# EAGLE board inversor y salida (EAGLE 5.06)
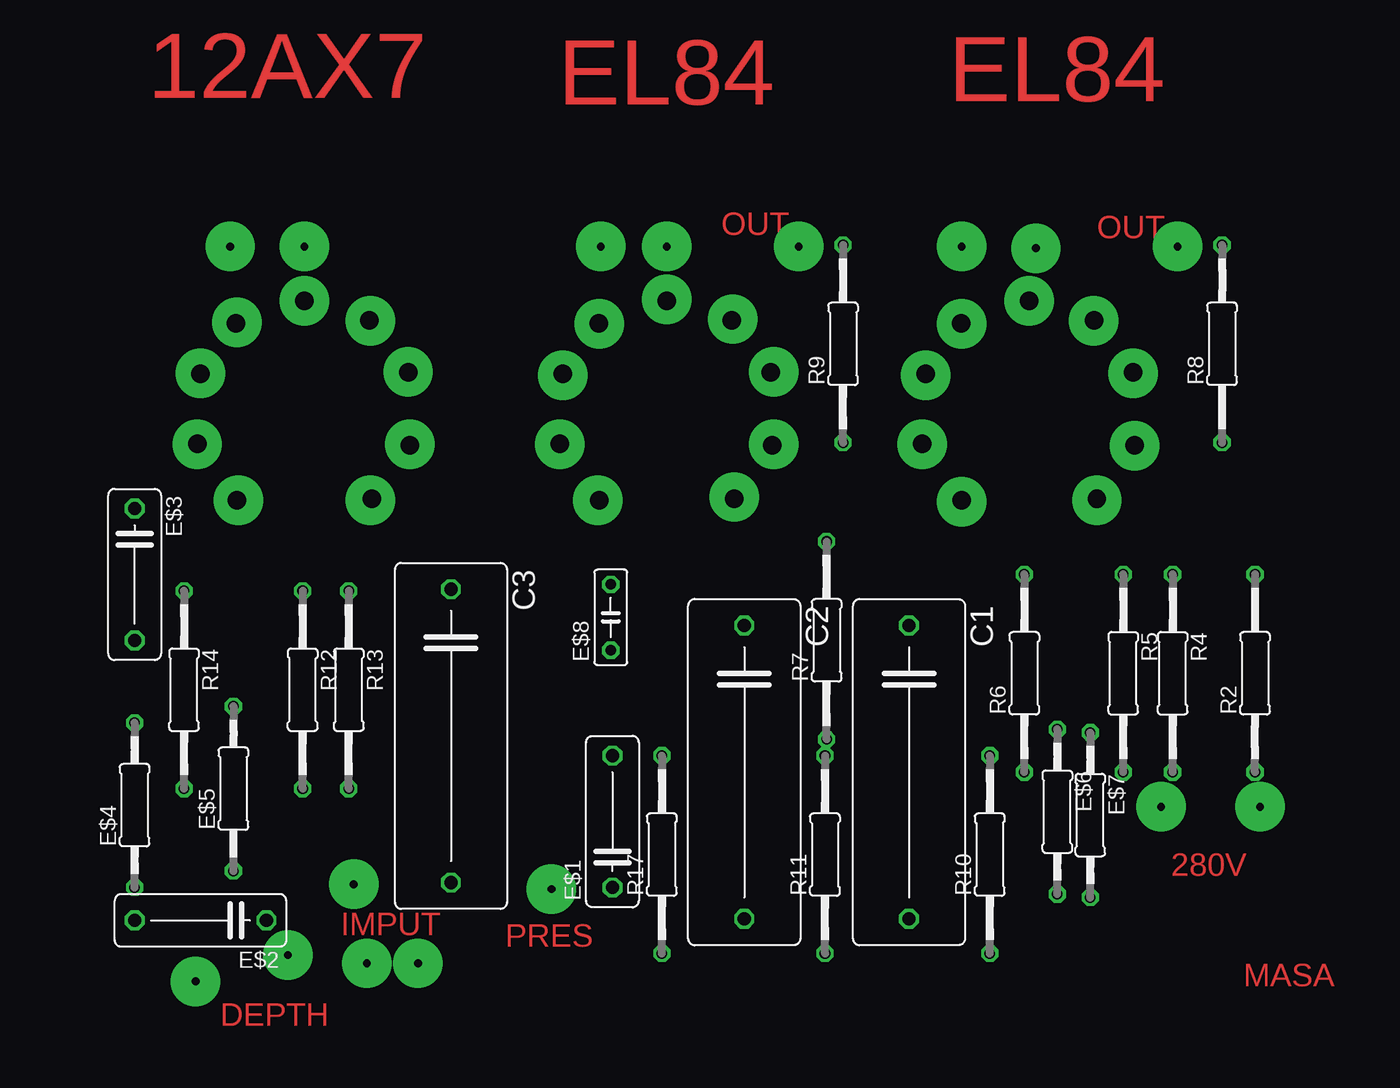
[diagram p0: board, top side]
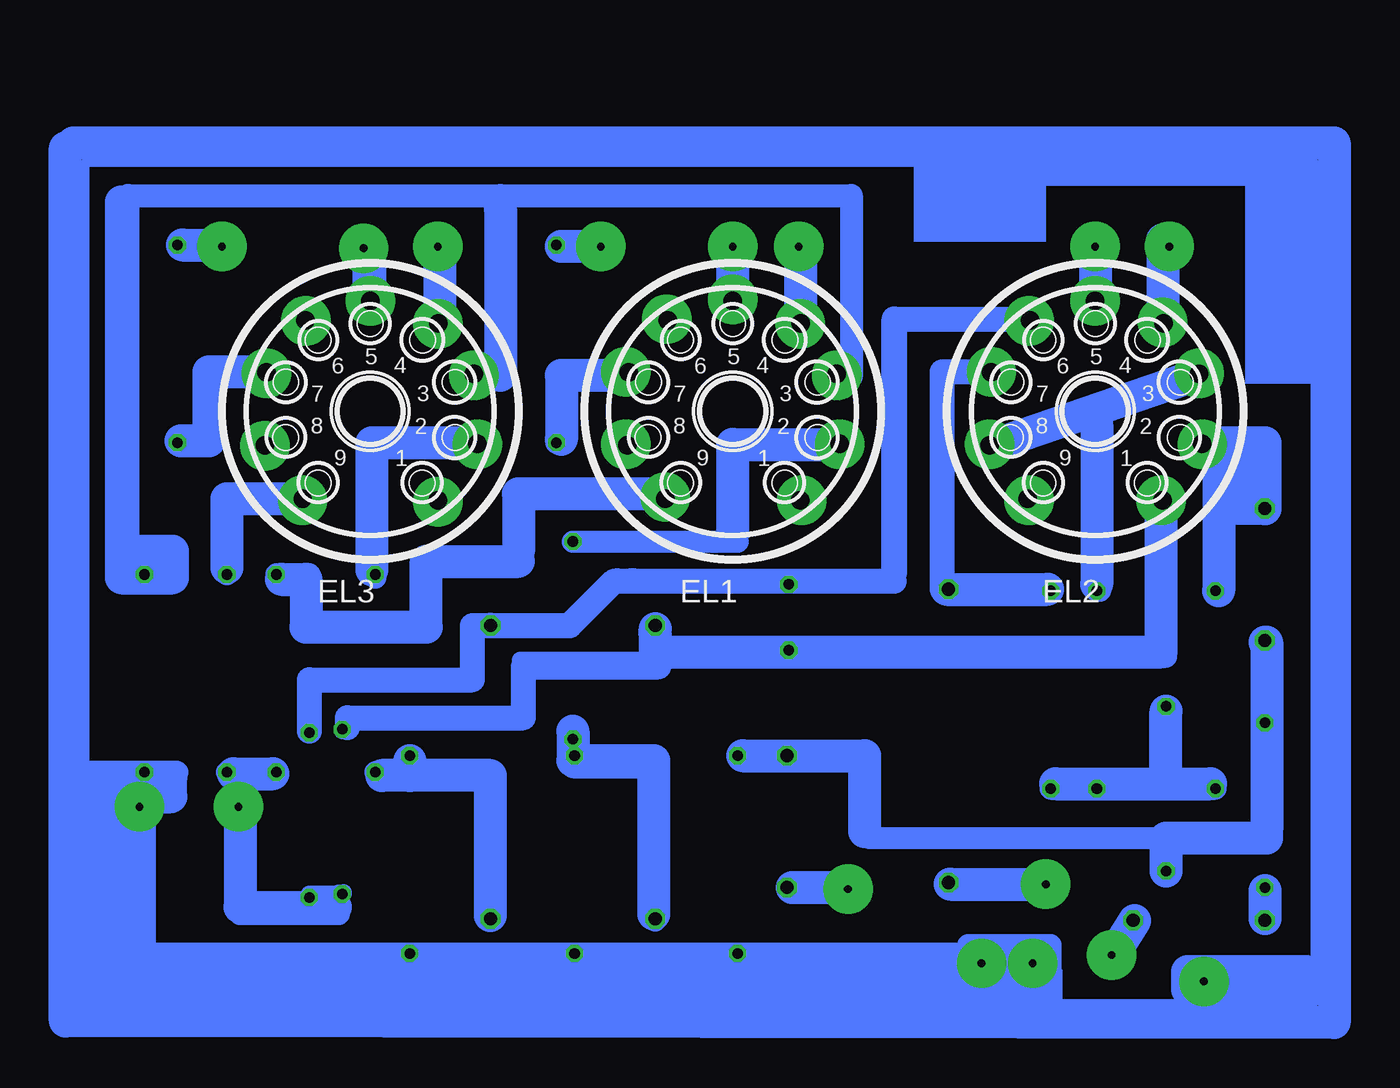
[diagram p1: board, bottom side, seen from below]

No outline drawn. Coordinates in mm, seen from the top.
Copper layers (1*16): Top 0.035mm / dielectric 1.5mm / Bottom 0.035mm
Design rules "default": minimum track width 10mil, minimum drill 24mil, track to track 8mil, track to pad 8mil, pad to pad 8mil, via to via 8mil, smd to smd 8mil, copper to edge 40mil, drill to drill 8mil, minimum pad ring 10mil, minimum via ring 8mil, stop-mask expansion 4mil, vias tented up to drill 0mil, thermal gap 10mil

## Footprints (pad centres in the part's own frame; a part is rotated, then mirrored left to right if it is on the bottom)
C225-087X268 = drill 1.016 octagon: 1 -11.303,0; 2 11.303,0
C102-043X133 = drill 1.016 octagon: 1 -5.08,0; 2 5.08,0
0207/12 = drill 0.813 octagon: 1 -6.35,0; 2 6.35,0
C050-025X075 = drill 0.813 octagon: 1 -2.54,0; 2 2.54,0
NOVAL = drill 1.422 pad 2.54 round: 1 5.207,-6.858; 2 8.254,-2.484; 3 8.004,2.893; 4 5.258,6.77; 5 0,8.524; 6 -5.004,7.024; 7 -8.004,3.02; 8 -8.127,-2.611; 9 -5.207,-6.731
0207/15 = drill 0.813 octagon: 1 -7.62,0; 2 7.62,0

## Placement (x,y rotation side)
C1  47NF  [C225-087X268]  -182.88,-422.91 270 top
C2  47NF  [C225-087X268]  -195.58,-422.91 270 top
C3  22NF  [C225-087X268]  -218.19,-420.12 270 top
E$1  100nF  [C102-043X133]  -205.74,-426.72 90 top
E$2  100nf  [C102-043X133]  -237.49,-434.34 180 top
E$3  100nf  [C102-043X133]  -242.57,-407.67 270 top
E$4  39k  [0207/12]  -242.57,-425.45 90 top
E$5  10k  [0207/12]  -234.95,-424.18 90 top
E$6  100k  [0207/12]  -171.45,-425.96 270 top
E$7  82k  [0207/12]  -168.91,-426.21 270 top
E$8  47PF  [C050-025X075]  -205.87,-410.97 90 top
EL1  [NOVAL]  -201.55,-395.1 0 bottom
EL2  [NOVAL]  -229.49,-395.1 0 bottom
EL3  [NOVAL]  -173.61,-395.1 0 bottom
R2  150 5W  [0207/15]  -156.21,-415.29 90 top
R4  470  [0207/15]  -162.56,-415.29 270 top
R5  470  [0207/15]  -166.37,-415.29 270 top
R6  10K  [0207/15]  -173.99,-415.29 90 top
R7  10K  [0207/15]  -189.23,-412.75 90 top
R8  120 2W  [0207/15]  -158.75,-389.89 90 top
R9  120 2W  [0207/15]  -187.96,-389.89 90 top
R10  100K  [0207/15]  -176.66,-429.26 90 top
R11  100K  [0207/15]  -189.36,-429.26 90 top
R12  470k  [0207/15]  -229.62,-416.56 270 top
R13  1M  [0207/15]  -226.06,-416.56 270 top
R14  1M  [0207/15]  -238.76,-416.56 270 top
R17  4K7  [0207/15]  -201.93,-429.26 90 top

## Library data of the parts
C1-C3 E$1-E$8 = rcl
EL1-EL3 = Tubes
R2 R4-R14 R17 = m-pad-2.1

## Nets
S$23: R4.1
S$24: R4.2 R5.2
S$25: R7.2
S$28: R8.1
S$30: R6.1
S$32: E$2.2 E$4.1
S$33: R5.1
S$34: R17.1
S$37: R13.1
S$38: R13.2 R14.2
S$40: R14.1
S$41: E$3.2 R17.2
S$42: E$1.1
S$48: R8.2
S$49: R9.1
S$50: R9.2

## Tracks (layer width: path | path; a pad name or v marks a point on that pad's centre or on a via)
S$17  (via drill 0.6 pad 3.81)
  other vias: -230.76,-437.01
S$21
  Bottom 1.778: -209.55,-392.43 -210.69,-392.43 -210.69,-378.46 -183.64,-378.46 | -181.61,-392.43 -183.64,-392.43 -183.64,-378.46 | -183.64,-378.46 -154.94,-378.46 -154.94,-405.89 -154.94,-407.67
  Bottom 2.54: -154.94,-405.89 -158.37,-405.89 -158.37,-407.92 -154.43,-407.92 -154.43,-407.04 | -158.37,-407.42 -154.43,-407.42 -154.43,-407.04 | -154.43,-378.97 -154.43,-407.04
S$22
  Bottom 1.93: -171.83,-418.85 -171.83,-419.48
S$23  (via drill 0.6 pad 3.81)
  Bottom 1.676: -168.91,-401.95 v-168.4,-401.95 -162.56,-401.95 -162.56,-407.16 R4.1
  Bottom 2.54: -168.28,-401.83 -162.56,-401.83 -162.56,-407.16
S$24
  Bottom 1.676: -163.83,-422.91 R5.2 | R4.2 -163.83,-422.91 | -163.83,-422.91 -163.83,-425.45
S$25
  Bottom 1.676: -209.55,-397.51 -201.93,-397.51 -201.93,-405.13 R7.2
S$26
  Bottom 1.676: -181.61,-397.51 -173.99,-397.51 -173.99,-407.92
S$27
  Bottom 1.676: -195.58,-434.34 -195.58,-422.53 -189.23,-422.53 -189.23,-419.74 -189.1,-419.74
  Bottom 2.54: -189.23,-419.74 -189.23,-422.02 -195.45,-422.02 -195.45,-433.83
S$28
  Bottom 1.676: -165.1,-391.92 -161.29,-391.92 -161.29,-397.51 R8.1
S$29  (via drill 0.6 pad 3.81)
  other vias: -224.41,-388.11
S$30
  Bottom 1.676: -182.88,-434.34 -182.88,-433.96 -182.88,-422.91 -176.53,-422.91 | R6.1 -176.53,-422.91 | -176.53,-422.91 -176.53,-421.64
  Bottom 2.54: -182.88,-433.96 -182.88,-423.16 -176.66,-423.16 | -176.66,-423.16 -174.5,-423.16 | -176.66,-423.16 -176.66,-422.02
S$31
  Bottom 1.676: -193.93,-408.05 -193.68,-408.05 | -193.93,-408.05 -214,-408.05 | -182.88,-411.48 -189.23,-411.48 -192.66,-408.05 -193.93,-408.05
S$32
  Bottom 1.676: -242.57,-434.21 E$2.2 | E$4.1 -242.57,-432.05
  Bottom 2.54: -242.57,-432.05 -242.57,-434.21
S$33
  Bottom 1.676: -196.34,-401.32 -185.42,-401.32 -185.42,-406.4 -177.8,-406.4 -177.8,-408.94 | -177.8,-408.94 -177.8,-412.12 -168.91,-412.12 -168.91,-407.67 R5.1 | -177.8,-408.94 -177.8,-407.67
S$34
  Bottom 1.676: -200.66,-436.88 R17.1 | -200.66,-436.88 -219.71,-436.88 | -219.71,-436.88 -222.25,-436.88 | -187.96,-436.88 -189.23,-436.88 | -187.96,-436.88 -200.66,-436.88 | -187.96,-436.88 -156.21,-436.88 -156.21,-435.61 | -153.67,-422.91 -156.21,-422.91 | -156.21,-422.91 -158.75,-422.91 | -156.21,-422.91 -156.21,-435.61 | -219.71,-436.88 -219.71,-436.25 -226.06,-436.25 -226.06,-438.15 -156.21,-438.15 -156.21,-435.61
S$35
  Bottom 1.676: -220.98,-397.51 -237.49,-392.43
S$36
  Bottom 1.676: -229.87,-394.97 -229.87,-408.94
S$37  (via drill 0.6 pad 3.81)
  Bottom 1.676: R13.1 -217.68,-408.94 -217.68,-408.81 | v-221.49,-392.05 -221.62,-392.05
  Bottom 1.93: v-221.49,-392.05 -217.68,-392.05 -217.68,-408.81
S$38
  Bottom 1.676: -229.87,-424.18 R13.2 -234.95,-424.18 | -234.95,-424.18 R14.2 | -234.95,-424.18 -234.95,-423.29 | -234.95,-418.21 -234.95,-417.83
  Bottom 2.54: -234.95,-423.29 -234.95,-418.21
S$39
  Bottom 1.676: -218.44,-431.8 -226.06,-431.8
S$40
  Bottom 1.676: -237.49,-397.51 -237.74,-397.51 -238.76,-397.51 -238.76,-402.59 | -242.57,-402.59 -238.76,-402.59 | -238.76,-402.59 R14.1
  Bottom 2.54: -242.57,-402.59 -239.14,-402.59 -239.14,-397.89 | -237.74,-397.51 -242.57,-397.51 -242.57,-402.59 | -242.57,-402.59 -239.52,-402.59 -239.52,-402.46 -240.54,-402.46 -240.54,-399.42
S$41
  Bottom 1.676: E$3.2 -242.57,-412.88 -242.57,-427.99 -234.95,-427.99 | -234.95,-427.99 -234.95,-428.37 | -234.95,-427.99 -212.09,-427.99 -212.09,-421.64 -211.71,-421.64 | R17.2 -202.31,-421.64
  Bottom 2.54: -242.57,-412.88 -242.7,-412.88 -242.7,-427.36 | -234.95,-428.37 -234.95,-430.53 | -234.95,-427.99 -242.7,-427.99 -242.7,-427.74 | -202.31,-421.64 -211.71,-421.64 -211.71,-427.48
S$42
  Bottom 1.676: E$1.1 -206.12,-431.8 | -210.57,-431.8 -210.82,-431.8
  Bottom 2.54: -206.12,-431.8 -210.57,-431.8
S$43
  Bottom 1.676: -232.41,-434.34 -231.14,-436.88
S$44
  Bottom 1.676: -207.01,-382.27 -207.01,-388.62
S$45
  Bottom 1.676: -201.93,-382.27 -201.93,-386.71
S$46
  Bottom 1.676: -179.07,-382.27 -179.07,-388.62
S$47
  Bottom 1.676: -173.99,-382.27 -173.99,-386.59
S$48
  Bottom 1.676: R8.2 -159.13,-382.27 | -162.18,-382.27 -162.56,-382.27
  Bottom 2.54: -159.13,-382.27 -162.18,-382.27
S$49
  Bottom 1.676: -193.04,-392.43 -187.96,-392.43 R9.1
S$50
  Bottom 1.676: -191.77,-382.27 -191.52,-382.27 R9.2
  Bottom 2.54: -191.52,-382.27 -191.52,-382.4 -188.34,-382.4
S$52  (via drill 0.6 pad 3.81)
  other vias: -235.2,-382.4
S$53  (via drill 0.6 pad 3.81)
  other vias: -229.49,-382.4
S$54  (via drill 0.6 pad 3.81)
  other vias: -206.63,-382.4
S$55  (via drill 0.6 pad 3.81)
  other vias: -191.39,-382.4
S$56  (via drill 0.6 pad 3.81)
  other vias: -178.82,-382.4
S$57  (via drill 0.6 pad 3.81)
  other vias: -173.1,-382.52
S$58  (via drill 0.6 pad 3.81)
  other vias: -162.18,-382.4
S$59  (via drill 0.6 pad 3.81)
  other vias: -163.45,-425.58
S$60  (via drill 0.6 pad 3.81)
  other vias: -155.83,-425.58
S$61  (via drill 0.6 pad 3.81)
  other vias: -210.44,-431.93
S$62  (via drill 0.6 pad 3.81)
  Bottom 2.54: -218.31,-431.55 v-225.68,-431.55
S$63  (via drill 0.6 pad 3.81)
  other vias: -224.66,-437.64
S$64
  Bottom 1.676: -229.87,-382.27 -229.87,-386.08
S$65
  Bottom 1.676: -234.95,-382.27 -234.95,-388.62
S$66  (via drill 0.6 pad 3.81)
  other vias: -201.55,-382.4
S$67
  Bottom 0.61: -151.64,-375.92 -151.64,-440.69 -246.38,-440.69 -246.38,-375.92 -151.64,-375.92
S$68
  Bottom 1.676: -171.2,-432.44 -171.2,-433.83 -163.58,-433.83 -163.58,-423.55
  Bottom 2.54: -170.94,-433.32 -163.58,-433.32 -163.58,-423.55
S$69
  Bottom 1.27: -181.36,-411.73 -181.36,-415.67 -168.91,-415.67 -168.91,-415.8 | -168.91,-419.74 -168.91,-419.86
  Bottom 1.676: -224.79,-387.99 -224.41,-387.99 -214.12,-387.99 -214.12,-407.67
  Bottom 1.93: -168.91,-419.74 -168.91,-415.8 -181.48,-415.8 -181.48,-411.61 -188.98,-411.61 -192.41,-408.18 -214,-408.18 -214,-387.99 -224.41,-387.99
S$70
  Bottom 1.27: -185.17,-418.59 -185.17,-414.27 -194.94,-414.27
S$71
  Bottom 1.27: -181.48,-411.73 -183.01,-411.73
S$72
  Bottom 1.27: -171.58,-432.18 -171.58,-432.31 -168.91,-432.31 -168.91,-432.82 | -168.91,-432.82 -168.91,-433.2 | -168.91,-432.82 -170.43,-432.82
S$73  (via drill 0.6 pad 3.81)
  Bottom 2.54: -229.49,-386.97 v-229.49,-386.59 -229.49,-382.14
S$74  (via drill 0.6 pad 3.81)
  Bottom 2.54: -234.82,-388.62 -234.7,-388.62 v-234.7,-388.24 -234.7,-381.89
S$75
  Bottom 2.54: -221.36,-397.76 -237.62,-392.18
S$76
  Bottom 2.54: -239.01,-398.91 -239.01,-408.94
S$77
  Bottom 2.54: -226.44,-423.8 -238.38,-423.8
S$78
  Bottom 2.54: -232.54,-434.34 -230.76,-437.13
S$79
  Bottom 2.54: -236.6,-439.67 -236.6,-438.28 -245.24,-438.28 -245.24,-439.55 -238.76,-439.55
S$80
  Bottom 1.27: -244.73,-437.64 -245.87,-437.64
S$81
  Bottom 2.54: -218.06,-408.81 -225.81,-408.81
S$82
  Bottom 2.54: -229.62,-396.11 -229.62,-408.43
S$83
  Bottom 2.54: -163.07,-423.04 -166.12,-423.04
S$84
  Bottom 2.54: -158.24,-423.29 -158.24,-424.81 -153.92,-424.81
S$85
  Bottom 1.27: -152.02,-422.66 -158.75,-422.66
S$86
  Bottom 1.27: -156.46,-427.61 -156.46,-425.45 -158.37,-425.45
S$87
  Bottom 2.54: -181.86,-397.51 -173.74,-397.51 -173.74,-407.29
S$88
  Bottom 2.54: -152.78,-423.55 -152.91,-423.55 -152.91,-439.55
S$89
  Bottom 2.54: -196.6,-401.45 -185.04,-401.45 -185.04,-405.89
S$90
  Bottom 2.54: -165.61,-392.05 -161.16,-392.05 -161.16,-397.38 -159,-397.38
S$91
  Bottom 2.54: -173.61,-386.71 -173.48,-386.71 -173.48,-382.52
S$92
  Bottom 2.54: -178.94,-382.4 -178.94,-388.49
S$93  (via drill 0.6 pad 3.81)
  Bottom 2.54: v-181.61,-392.3 -183.64,-392.3 -183.64,-379.48
S$94
  Bottom 2.54: -193.55,-392.3 -188.34,-392.3 -188.34,-397.26
S$95  (via drill 0.6 pad 3.81)
  Bottom 2.54: -206.63,-382.27 -206.76,-382.27 v-206.76,-388.37
S$96  (via drill 0.6 pad 3.81)
  Bottom 2.54: -201.55,-386.97 v-201.55,-386.46 -201.55,-382.27
S$97  (via drill 0.6 pad 3.81)
  Bottom 2.54: -209.93,-397.64 v-209.8,-397.64 -201.55,-397.64 -201.55,-404.5
S$98
  Bottom 2.54: -185.04,-406.65 -177.93,-406.65 -177.93,-411.73 -168.66,-411.73 -168.66,-408.05 -166.75,-408.05
S$99  (via drill 0.6 pad 3.81)
  Bottom 1.676: -234.95,-401.32 -234.95,-414.02 -195.58,-414.02 | -195.58,-414.02 -195.45,-414.02 | -195.58,-411.86 -195.58,-411.48 | -195.58,-413.64 -195.58,-414.02
  Bottom 1.93: -171.83,-418.72 -185.42,-418.72 -185.42,-414.78 -195.83,-414.78 -195.83,-412.37 -195.58,-412.37
  Bottom 2.54: v-234.57,-401.95 -234.57,-413.64 -195.58,-413.64 -195.58,-412.37 -195.58,-411.86
S$100
  Bottom 1.27: -171.7,-418.59 -171.45,-419.74
S$101  (via drill 0.6 pad 3.81)
  other vias: -221.36,-397.64
S$102  (via drill 0.6 pad 3.81)
  other vias: -224.41,-401.95
S$103  (via drill 0.6 pad 3.81)
  other vias: -237.74,-397.64
S$104  (via drill 0.6 pad 3.81)
  other vias: -237.49,-392.18
S$105  (via drill 0.6 pad 3.81)
  other vias: -206.88,-401.95
S$106  (via drill 0.6 pad 3.81)
  other vias: -209.55,-392.3
S$107  (via drill 0.6 pad 3.81)
  other vias: -196.47,-387.99
S$108  (via drill 0.6 pad 3.81)
  other vias: -193.29,-392.05
S$109  (via drill 0.6 pad 3.81)
  other vias: -193.29,-397.64
S$110  (via drill 0.6 pad 3.81)
  other vias: -196.34,-401.7
S$111  (via drill 0.6 pad 3.81)
  other vias: -178.82,-402.08
S$112  (via drill 0.6 pad 3.81)
  other vias: -181.86,-397.64
S$113  (via drill 0.6 pad 3.81)
  other vias: -178.82,-388.37
S$114  (via drill 0.6 pad 3.81)
  other vias: -173.61,-386.59
S$115  (via drill 0.6 pad 3.81)
  other vias: -168.66,-388.11
S$116  (via drill 0.6 pad 3.81)
  other vias: -165.61,-392.18
S$117  (via drill 0.6 pad 3.81)
  other vias: -165.48,-397.76
S$118
  Bottom 2.54: -150.11,-374.78 -150.11,-442.09 -247.9,-442.21 -247.9,-374.4 -150.75,-374.4
S$265  (via drill 0.6 pad 3.81)
  other vias: -237.87,-439.04
S$267  (via drill 0.6 pad 3.81)
  other vias: -220.73,-437.64
(copper drawn outside any net)
  shapes: Bottom area x5

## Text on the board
Top: 12AX7 | EL84 | EL84 | OUT | OUT | 280V | IMPUT | PRES | MASA | DEPTH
